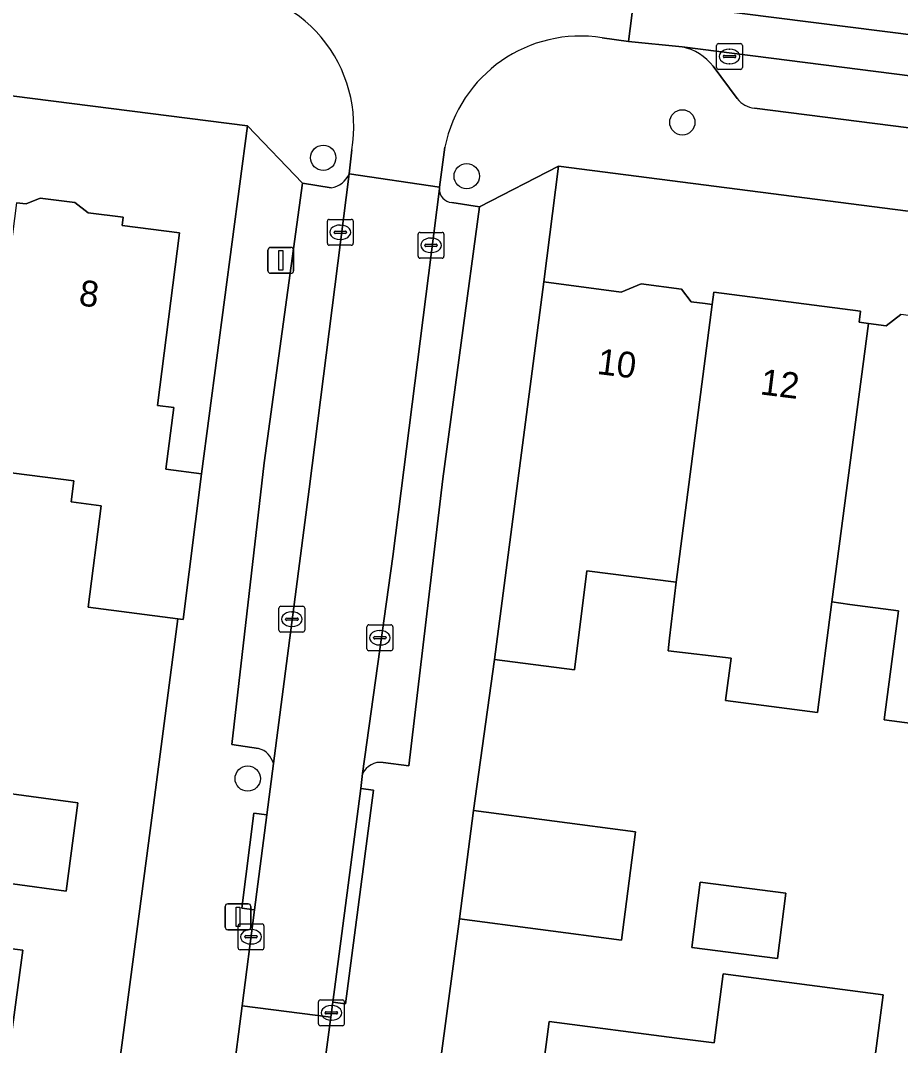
# Model space of a CAD drawing. Extents: x 161692 to 162379, y 380760 to 381678.
# Drawn here: x 161850.58 to 161884.64, y 381277.07 to 381316.74 of the extents above; entities that cross this region are included whole.
import ezdxf

# ---------------------------------------------------------------- set-up
doc = ezdxf.new("R2010")
doc.units = 0
for name, color, linetype in [('IMGEO_Boom', 7, 'Continuous'), ('IMGEO_Erf', 7, 'Continuous'), ('IMGEO_Kolk', 7, 'Continuous'), ('IMGEO_Lichtmast', 7, 'Continuous'), ('IMGEO_Muur', 7, 'Continuous'), ('IMGEO_Pand', 7, 'Continuous'), ('IMGEO_Pand_nummerreeks', 7, 'Continuous'), ('IMGEO_Parkeervlak_open', 7, 'Continuous'), ('IMGEO_Rijbaan_lokaal_gesloten', 7, 'Continuous'), ('IMGEO_Rijbaan_lokaal_open', 7, 'Continuous'), ('IMGEO_Voetpad_open', 7, 'Continuous')]:
    doc.layers.add(name, color=color, linetype=linetype)

msp = doc.modelspace()

# ---------------------------------------------------------------- linework, layer by layer
at = {"layer": 'IMGEO_Boom'}
for centre in [(161876.196, 381312.798), (161862.3, 381311.429), (161867.852, 381310.715), (161859.377, 381287.397)]:
    msp.add_circle(centre, 0.489, dxfattribs=at)
at = {"layer": 'IMGEO_Erf'}
for points in [[(161850.431, 381309.684), (161850.806, 381309.639), (161851.344, 381309.865), (161852.688, 381309.694), (161853.205, 381309.3), (161854.554, 381309.129), (161854.513, 381308.81), (161856.739, 381308.526), (161855.887, 381301.844), (161856.513, 381301.764), (161856.207, 381299.373), (161857.595, 381299.195), (161859.366, 381312.667), (161794.522, 381320.92)], [(161918.702, 381305.015), (161871.402, 381311.107), (161870.842, 381306.622), (161873.833, 381306.231), (161874.599, 381306.549), (161876.165, 381306.344), (161876.542, 381305.853), (161877.083, 381305.783), (161877.356, 381305.748), (161877.419, 381306.232), (161883.096, 381305.49), (161883.04, 381305.064), (161883.395, 381305.018), (161884.088, 381304.927), (161884.656, 381305.363)], [(161846.597, 381255.358), (161851.558, 381254.696), (161855.69, 381286.076), (161856.679, 381293.585), (161853.206, 381294.027), (161853.707, 381297.959), (161852.542, 381298.108), (161852.646, 381298.927), (161849.101, 381299.379)], [(161887.445, 381289.22), (161884.008, 381289.67), (161884.561, 381293.896), (161882.676, 381294.142), (161881.985, 381294.233), (161881.426, 381289.955), (161877.866, 381290.421), (161878.083, 381292.063), (161875.642, 381292.345), (161875.701, 381292.836), (161875.952, 381295.006), (161872.506, 381295.434), (161872.017, 381291.601), (161868.93, 381292.005), (161868.119, 381286.163), (161874.39, 381285.342), (161873.841, 381281.144), (161867.57, 381281.964), (161863.942, 381254.866), (161868.901, 381254.224), (161873.749, 381253.597), (161873.283, 381250)], [(161847.85, 381287.123), (161852.805, 381286.461), (161852.347, 381283.04), (161850.275, 381283.317)], [(161849.945, 381280.847), (161850.672, 381280.75), (161850.222, 381277.386)]]:
    msp.add_lwpolyline(points, dxfattribs=at)
for points in [[(161876.559, 381280.863), (161876.887, 381283.39), (161880.204, 381282.959), (161879.876, 381280.432)], [(161882.883, 381270.739), (161879.639, 381271.161), (161878.902, 381265.474), (161882.288, 381265.036), (161881.578, 381259.552), (161880.818, 381253.683), (161877.433, 381254.122), (161873.054, 381254.689), (161868.095, 381255.331), (161868.859, 381261.205), (161869.572, 381266.687), (161870.311, 381272.374), (161871.041, 381277.988), (161875.988, 381277.348), (161877.428, 381277.162), (161877.775, 381279.835), (161883.962, 381279.032)]]:
    msp.add_lwpolyline(points, close=True, dxfattribs=at)
at = {"layer": 'IMGEO_Kolk'}
for p, q in [((161877.522, 381314.922), (161877.522, 381315.774)), ((161877.597, 381315.848), (161878.449, 381315.848)), ((161878.01, 381315.628), (161878.035, 381315.628)), ((161878.523, 381315.774), (161878.523, 381314.922)), ((161877.781, 381315.342), (161877.781, 381315.354)), ((161878.219, 381315.305), (161877.821, 381315.305)), ((161877.824, 381315.391), (161878.222, 381315.391)), ((161878.265, 381315.354), (161878.265, 381315.342)), ((161878.449, 381314.848), (161877.597, 381314.848)), ((161878.033, 381315.068), (161878.008, 381315.068)), ((161862.46, 381308.117), (161862.46, 381308.969)), ((161862.535, 381309.043), (161863.387, 381309.043)), ((161862.948, 381308.823), (161862.973, 381308.823)), ((161863.461, 381308.969), (161863.461, 381308.117)), ((161862.719, 381308.537), (161862.719, 381308.549)), ((161863.157, 381308.5), (161862.759, 381308.5)), ((161862.762, 381308.586), (161863.16, 381308.586)), ((161863.203, 381308.549), (161863.203, 381308.537)), ((161865.971, 381307.614), (161865.971, 381308.466)), ((161866.046, 381308.54), (161866.898, 381308.54)), ((161866.972, 381308.466), (161866.972, 381307.614)), ((161863.387, 381308.043), (161862.535, 381308.043)), ((161862.971, 381308.263), (161862.946, 381308.263)), ((161866.23, 381308.034), (161866.23, 381308.046)), ((161866.273, 381308.083), (161866.671, 381308.083)), ((161866.459, 381308.32), (161866.484, 381308.32)), ((161866.714, 381308.046), (161866.714, 381308.034)), ((161866.668, 381307.997), (161866.27, 381307.997)), ((161866.482, 381307.76), (161866.457, 381307.76)), ((161866.898, 381307.54), (161866.046, 381307.54)), ((161860.586, 381293.14), (161860.586, 381293.992)), ((161860.661, 381294.066), (161861.513, 381294.066)), ((161861.074, 381293.846), (161861.099, 381293.846)), ((161861.587, 381293.992), (161861.587, 381293.14)), ((161860.845, 381293.56), (161860.845, 381293.572)), ((161861.283, 381293.523), (161860.885, 381293.523)), ((161860.888, 381293.609), (161861.286, 381293.609)), ((161861.329, 381293.572), (161861.329, 381293.56)), ((161864.067, 381293.348), (161864.919, 381293.348)), ((161861.513, 381293.066), (161860.661, 381293.066)), ((161861.097, 381293.286), (161861.072, 381293.286)), ((161863.992, 381292.422), (161863.992, 381293.274)), ((161864.48, 381293.128), (161864.505, 381293.128)), ((161864.993, 381293.274), (161864.993, 381292.422)), ((161864.251, 381292.842), (161864.251, 381292.854)), ((161864.689, 381292.805), (161864.291, 381292.805)), ((161864.294, 381292.891), (161864.692, 381292.891)), ((161864.503, 381292.568), (161864.478, 381292.568)), ((161864.735, 381292.854), (161864.735, 381292.842)), ((161864.919, 381292.348), (161864.067, 381292.348)), ((161859.004, 381280.848), (161859.004, 381281.7)), ((161859.079, 381281.774), (161859.931, 381281.774)), ((161859.492, 381281.554), (161859.517, 381281.554)), ((161860.005, 381281.7), (161860.005, 381280.848)), ((161859.263, 381281.268), (161859.263, 381281.28)), ((161859.701, 381281.231), (161859.303, 381281.231)), ((161859.306, 381281.317), (161859.704, 381281.317)), ((161859.747, 381281.28), (161859.747, 381281.268)), ((161859.931, 381280.774), (161859.079, 381280.774)), ((161859.515, 381280.994), (161859.49, 381280.994)), ((161862.115, 381277.903), (161862.115, 381278.755)), ((161862.19, 381278.829), (161863.042, 381278.829)), ((161863.116, 381278.755), (161863.116, 381277.903)), ((161862.374, 381278.323), (161862.374, 381278.335)), ((161862.812, 381278.286), (161862.414, 381278.286)), ((161862.417, 381278.372), (161862.815, 381278.372)), ((161862.603, 381278.609), (161862.628, 381278.609)), ((161862.858, 381278.335), (161862.858, 381278.323)), ((161862.626, 381278.049), (161862.601, 381278.049)), ((161863.042, 381277.829), (161862.19, 381277.829))]:
    msp.add_line(p, q, dxfattribs=at)
for points in [[(161877.522, 381314.922), (161877.522, 381315.774)], [(161877.597, 381315.848), (161878.449, 381315.848)], [(161878.523, 381315.774), (161878.523, 381314.922)], [(161878.449, 381314.848), (161877.597, 381314.848)], [(161862.46, 381308.117), (161862.46, 381308.969)], [(161862.535, 381309.043), (161863.387, 381309.043)], [(161863.461, 381308.969), (161863.461, 381308.117)], [(161865.971, 381307.614), (161865.971, 381308.466)], [(161866.046, 381308.54), (161866.898, 381308.54)], [(161866.972, 381308.466), (161866.972, 381307.614)], [(161863.387, 381308.043), (161862.535, 381308.043)], [(161866.898, 381307.54), (161866.046, 381307.54)], [(161860.586, 381293.14), (161860.586, 381293.992)], [(161860.661, 381294.066), (161861.513, 381294.066)], [(161861.587, 381293.992), (161861.587, 381293.14)], [(161864.067, 381293.348), (161864.919, 381293.348)], [(161861.513, 381293.066), (161860.661, 381293.066)], [(161863.992, 381292.422), (161863.992, 381293.274)], [(161864.993, 381293.274), (161864.993, 381292.422)], [(161864.919, 381292.348), (161864.067, 381292.348)], [(161859.004, 381280.848), (161859.004, 381281.7)], [(161859.079, 381281.774), (161859.931, 381281.774)], [(161860.005, 381281.7), (161860.005, 381280.848)], [(161859.931, 381280.774), (161859.079, 381280.774)], [(161862.115, 381277.903), (161862.115, 381278.755)], [(161862.19, 381278.829), (161863.042, 381278.829)], [(161863.116, 381278.755), (161863.116, 381277.903)], [(161863.042, 381277.829), (161862.19, 381277.829)]]:
    msp.add_lwpolyline(points, dxfattribs=at)
for centre, radius, start, end in [((161877.599, 381315.772), 0.0765, 91.552, 178.448), ((161877.599, 381315.772), 0.0765, 91.552, 178.448), ((161878.447, 381315.772), 0.0765, 1.552, 88.448), ((161878.447, 381315.772), 0.0765, 1.552, 88.448), ((161877.821, 381315.351), 0.0403, 85.8775, 175.7526), ((161877.818, 381315.341), 0.0366, 178.938, 274.7102), ((161878.222, 381315.348), 0.043, 264.8664, 352.4533), ((161878.226, 381315.353), 0.0386, 1.7309, 96.639), ((161877.599, 381314.924), 0.0765, 181.552, 268.448), ((161877.599, 381314.924), 0.0765, 181.552, 268.448), ((161878.447, 381314.924), 0.0765, 271.552, 358.448), ((161878.447, 381314.924), 0.0765, 271.552, 358.448), ((161862.537, 381308.967), 0.0765, 91.552, 178.448), ((161862.537, 381308.967), 0.0765, 91.552, 178.448), ((161863.385, 381308.967), 0.0765, 1.552, 88.448), ((161863.385, 381308.967), 0.0765, 1.552, 88.448), ((161862.759, 381308.546), 0.0403, 85.8775, 175.7526), ((161862.756, 381308.536), 0.0366, 178.938, 274.7102), ((161863.16, 381308.543), 0.043, 264.8664, 352.4533), ((161863.164, 381308.548), 0.0386, 1.7309, 96.639), ((161866.048, 381308.464), 0.0765, 91.552, 178.448), ((161866.048, 381308.464), 0.0765, 91.552, 178.448), ((161866.896, 381308.464), 0.0765, 1.552, 88.448), ((161866.896, 381308.464), 0.0765, 1.552, 88.448), ((161862.537, 381308.119), 0.0765, 181.552, 268.448), ((161862.537, 381308.119), 0.0765, 181.552, 268.448), ((161863.385, 381308.119), 0.0765, 271.552, 358.448), ((161863.385, 381308.119), 0.0765, 271.552, 358.448), ((161866.27, 381308.043), 0.0403, 85.8775, 175.7526), ((161866.267, 381308.033), 0.0366, 178.938, 274.7102), ((161866.671, 381308.04), 0.043, 264.8664, 352.4533), ((161866.675, 381308.045), 0.0386, 1.7309, 96.639), ((161866.048, 381307.616), 0.0765, 181.552, 268.448), ((161866.048, 381307.616), 0.0765, 181.552, 268.448), ((161866.896, 381307.616), 0.0765, 271.552, 358.448), ((161866.896, 381307.616), 0.0765, 271.552, 358.448), ((161860.663, 381293.99), 0.0765, 91.552, 178.448), ((161860.663, 381293.99), 0.0765, 91.552, 178.448), ((161861.511, 381293.99), 0.0765, 1.552, 88.448), ((161861.511, 381293.99), 0.0765, 1.552, 88.448), ((161860.885, 381293.569), 0.0403, 85.8775, 175.7526), ((161860.882, 381293.559), 0.0366, 178.938, 274.7102), ((161861.286, 381293.566), 0.043, 264.8664, 352.4533), ((161861.29, 381293.571), 0.0386, 1.7309, 96.639), ((161864.069, 381293.272), 0.0765, 91.552, 178.448), ((161864.069, 381293.272), 0.0765, 91.552, 178.448), ((161864.917, 381293.272), 0.0765, 1.552, 88.448), ((161864.917, 381293.272), 0.0765, 1.552, 88.448), ((161860.663, 381293.142), 0.0765, 181.552, 268.448), ((161860.663, 381293.142), 0.0765, 181.552, 268.448), ((161861.511, 381293.142), 0.0765, 271.552, 358.448), ((161861.511, 381293.142), 0.0765, 271.552, 358.448), ((161864.291, 381292.851), 0.0403, 85.8775, 175.7526), ((161864.288, 381292.841), 0.0366, 178.938, 274.7102), ((161864.692, 381292.848), 0.043, 264.8664, 352.4533), ((161864.696, 381292.853), 0.0386, 1.7309, 96.639), ((161864.069, 381292.424), 0.0765, 181.552, 268.448), ((161864.069, 381292.424), 0.0765, 181.552, 268.448), ((161864.917, 381292.424), 0.0765, 271.552, 358.448), ((161864.917, 381292.424), 0.0765, 271.552, 358.448), ((161859.081, 381281.698), 0.0765, 91.552, 178.448), ((161859.081, 381281.698), 0.0765, 91.552, 178.448), ((161859.929, 381281.698), 0.0765, 1.552, 88.448), ((161859.929, 381281.698), 0.0765, 1.552, 88.448), ((161859.303, 381281.277), 0.0403, 85.8775, 175.7526), ((161859.3, 381281.267), 0.0366, 178.938, 274.7102), ((161859.704, 381281.274), 0.043, 264.8664, 352.4533), ((161859.708, 381281.279), 0.0386, 1.7309, 96.639), ((161859.081, 381280.85), 0.0765, 181.552, 268.448), ((161859.081, 381280.85), 0.0765, 181.552, 268.448), ((161859.929, 381280.85), 0.0765, 271.552, 358.448), ((161859.929, 381280.85), 0.0765, 271.552, 358.448), ((161862.192, 381278.753), 0.0765, 91.552, 178.448), ((161862.192, 381278.753), 0.0765, 91.552, 178.448), ((161863.04, 381278.753), 0.0765, 1.552, 88.448), ((161863.04, 381278.753), 0.0765, 1.552, 88.448), ((161862.414, 381278.332), 0.0403, 85.8775, 175.7526), ((161862.411, 381278.322), 0.0366, 178.938, 274.7102), ((161862.815, 381278.329), 0.043, 264.8664, 352.4533), ((161862.819, 381278.334), 0.0386, 1.7309, 96.639), ((161862.192, 381277.905), 0.0765, 181.552, 268.448), ((161862.192, 381277.905), 0.0765, 181.552, 268.448), ((161863.04, 381277.905), 0.0765, 271.552, 358.448), ((161863.04, 381277.905), 0.0765, 271.552, 358.448)]:
    msp.add_arc(centre, radius, start, end, dxfattribs=at)
for centre, major_axis, ratio, start_param, end_param in [((161878.009, 381315.348), (-0.387, 0.002), 0.722429, 4.712389, 7.853982), ((161878.034, 381315.348), (-0.39, 0.002), 0.717154, 1.570796, 4.712389), ((161862.947, 381308.543), (-0.387, 0.002), 0.722429, 4.712389, 7.853982), ((161862.972, 381308.543), (-0.39, 0.002), 0.717154, 1.570796, 4.712389), ((161866.458, 381308.04), (-0.387, 0.002), 0.722429, 4.712389, 7.853982), ((161866.483, 381308.04), (-0.39, 0.002), 0.717154, 1.570796, 4.712389), ((161861.073, 381293.566), (-0.387, 0.002), 0.722429, 4.712389, 7.853982), ((161861.098, 381293.566), (-0.39, 0.002), 0.717154, 1.570796, 4.712389), ((161864.479, 381292.848), (-0.387, 0.002), 0.722429, 4.712389, 7.853982), ((161864.504, 381292.848), (-0.39, 0.002), 0.717154, 1.570796, 4.712389), ((161859.491, 381281.274), (-0.387, 0.002), 0.722429, 4.712389, 7.853982), ((161859.516, 381281.274), (-0.39, 0.002), 0.717154, 1.570796, 4.712389), ((161862.602, 381278.329), (-0.387, 0.002), 0.722429, 4.712389, 7.853982), ((161862.627, 381278.329), (-0.39, 0.002), 0.717154, 1.570796, 4.712389)]:
    msp.add_ellipse(centre, major_axis=major_axis, ratio=ratio, start_param=start_param, end_param=end_param, dxfattribs=at)
at = {"layer": 'IMGEO_Lichtmast'}
for p, q in [((161860.162, 381307.057), (161860.162, 381307.857)), ((161860.162, 381307.857), (161860.162, 381307.057)), ((161860.262, 381307.957), (161861.052, 381307.957)), ((161861.052, 381307.957), (161860.262, 381307.957)), ((161861.152, 381307.857), (161861.152, 381307.057)), ((161861.152, 381307.057), (161861.152, 381307.857)), ((161861.052, 381306.957), (161860.262, 381306.957)), ((161860.262, 381306.957), (161861.052, 381306.957)), ((161858.506, 381281.646), (161858.506, 381282.446)), ((161858.506, 381282.446), (161858.506, 381281.646)), ((161858.606, 381282.546), (161859.396, 381282.546)), ((161859.396, 381282.546), (161858.606, 381282.546)), ((161859.496, 381282.446), (161859.496, 381281.646)), ((161859.496, 381281.646), (161859.496, 381282.446)), ((161859.396, 381281.546), (161858.606, 381281.546)), ((161858.606, 381281.546), (161859.396, 381281.546))]:
    msp.add_line(p, q, dxfattribs=at)
for points in [[(161860.582, 381307.832), (161860.732, 381307.832), (161860.732, 381307.082), (161860.582, 381307.082), (161860.582, 381307.832)], [(161858.926, 381282.421), (161859.076, 381282.421), (161859.076, 381281.671), (161858.926, 381281.671), (161858.926, 381282.421)]]:
    msp.add_lwpolyline(points, dxfattribs=at)
for centre, start, end in [((161860.262, 381307.857), 90, 180), ((161860.262, 381307.857), 90, 180), ((161861.052, 381307.857), 0, 90), ((161861.052, 381307.857), 360, 90), ((161860.262, 381307.057), 180, 270), ((161860.262, 381307.057), 180, 270), ((161861.052, 381307.057), 270, 0), ((161861.052, 381307.057), 270, 0), ((161858.606, 381282.446), 90, 180), ((161858.606, 381282.446), 90, 180), ((161859.396, 381282.446), 0, 90), ((161859.396, 381282.446), 360, 90), ((161858.606, 381281.646), 180, 270), ((161858.606, 381281.646), 180, 270), ((161859.396, 381281.646), 270, 0), ((161859.396, 381281.646), 270, 0)]:
    msp.add_arc(centre, 0.1, start, end, dxfattribs=at)
at = {"layer": 'IMGEO_Muur'}
for points in [[(161856.679, 381293.585), (161855.69, 381286.076)], [(161868.93, 381292.005), (161868.119, 381286.163)]]:
    msp.add_lwpolyline(points, dxfattribs=at)
at = {"layer": 'IMGEO_Pand'}
for points in [[(161849.101, 381299.379), (161852.646, 381298.927), (161852.542, 381298.108), (161853.707, 381297.959), (161853.206, 381294.027), (161856.679, 381293.585), (161856.876, 381293.56), (161857.595, 381299.195), (161856.207, 381299.373), (161856.513, 381301.764), (161855.887, 381301.844), (161856.739, 381308.526), (161854.513, 381308.81), (161854.554, 381309.129), (161853.205, 381309.3), (161852.688, 381309.694), (161851.344, 381309.865), (161850.806, 381309.639), (161850.431, 381309.684)], [(161877.356, 381305.748), (161877.083, 381305.783), (161876.542, 381305.853), (161876.165, 381306.344), (161874.599, 381306.549), (161873.833, 381306.231), (161870.842, 381306.622), (161868.93, 381292.005), (161872.017, 381291.601), (161872.506, 381295.434), (161875.952, 381295.006)], [(161883.395, 381305.018), (161883.04, 381305.064), (161883.096, 381305.49), (161877.419, 381306.232), (161877.356, 381305.748), (161875.952, 381295.006), (161875.701, 381292.836), (161875.642, 381292.345), (161878.083, 381292.063), (161877.866, 381290.421), (161881.426, 381289.955), (161881.985, 381294.233)], [(161889.792, 381304.253), (161886.702, 381304.657), (161886.327, 381305.144), (161884.656, 381305.363), (161884.088, 381304.927), (161883.395, 381305.018), (161881.985, 381294.233), (161882.676, 381294.142), (161884.561, 381293.896), (161884.008, 381289.67), (161887.445, 381289.22), (161887.821, 381289.171)], [(161838.404, 381284.864), (161836.685, 381285.121), (161836.322, 381282.331), (161835.92, 381279.248), (161839.658, 381278.761), (161850.222, 381277.386), (161850.672, 381280.75), (161849.945, 381280.847), (161850.275, 381283.317), (161852.347, 381283.04), (161852.805, 381286.461), (161847.85, 381287.123), (161847.313, 381287.195), (161846.846, 381283.703), (161842.013, 381284.349), (161840.434, 381284.56)], [(161868.119, 381286.163), (161867.57, 381281.964), (161873.841, 381281.144), (161874.39, 381285.342)], [(161876.559, 381280.863), (161879.876, 381280.432), (161880.204, 381282.959), (161876.887, 381283.39)], [(161870.311, 381272.374), (161879.639, 381271.161), (161882.883, 381270.739), (161883.962, 381279.032), (161877.775, 381279.835), (161877.428, 381277.162), (161875.988, 381277.348), (161871.041, 381277.988)]]:
    msp.add_lwpolyline(points, close=True, dxfattribs=at)
at = {"layer": 'IMGEO_Parkeervlak_open'}
for points in [[(161917.21, 381310.5), (161876.187, 381315.72)], [(161877.391, 381314.969), (161878.321, 381313.716)], [(161878.988, 381313.353), (161913.61, 381308.931)], [(161860.369, 381287.975), (161861.761, 381298.603), (161863.306, 381310.81)], [(161862.608, 381310.266), (161861.491, 381310.444), (161860.014, 381299.613), (161858.769, 381288.718), (161859.797, 381288.563)], [(161866.793, 381310.228), (161864.987, 381295.988), (161863.824, 381287.593)], [(161866.932, 381299.002), (161868.344, 381309.528), (161867.278, 381309.693)], [(161864.621, 381288.019), (161865.611, 381287.89), (161866.932, 381299.002)]]:
    msp.add_lwpolyline(points, dxfattribs=at)
for centre, radius, start, end in [((161875.79, 381313.743), 2.016, 37.442, 78.6499), ((161879.062, 381314.284), 0.934, 217.4585, 265.4289), ((161862.472, 381311.16), 0.904, 278.6254, 337.2381), ((161867.315, 381310.214), 0.523, 178.4991, 265.8882), ((161859.591, 381287.79), 0.8, 13.366, 75.0536), ((161864.518, 381287.254), 0.772, 82.2985, 153.9509)]:
    msp.add_arc(centre, radius, start, end, dxfattribs=at)
at = {"layer": 'IMGEO_Rijbaan_lokaal_gesloten'}
msp.add_lwpolyline([(161924.113, 381311.254), (161874.322, 381317.556), (161874.117, 381315.93), (161876.187, 381315.72), (161917.21, 381310.5), (161917.275, 381310.497), (161923.115, 381309.763), (161949.317, 381306.399), (161975.89, 381302.987), (162013.612, 381298.115), (162013.834, 381299.74), (161976.139, 381304.58)], close=True, dxfattribs=at)
at = {"layer": 'IMGEO_Rijbaan_lokaal_open'}
for points in [[(161873.096, 381316.072), (161874.117, 381315.93), (161874.322, 381317.556), (161874.551, 381319.364), (161874.726, 381320.753), (161875.004, 381322.955)], [(161863.408, 381311.731), (161863.306, 381310.81), (161866.801, 381310.288), (161867.011, 381311.834)]]:
    msp.add_lwpolyline(points, dxfattribs=at)
for points in [[(161874.551, 381319.364), (161874.322, 381317.556), (161924.113, 381311.254), (161976.139, 381304.58), (162013.834, 381299.74), (162014.081, 381301.54), (161976.129, 381306.423), (161924.33, 381313.049)], [(161864.987, 381295.988), (161866.793, 381310.228), (161866.801, 381310.288), (161863.306, 381310.81), (161861.761, 381298.603), (161860.369, 381287.975), (161860.114, 381285.992), (161859.641, 381282.316), (161859.161, 381278.6), (161862.595, 381278.164), (161862.671, 381278.748), (161863.751, 381287.017), (161863.824, 381287.593)], [(161859.161, 381278.6), (161858.787, 381275.704), (161858.749, 381275.573), (161862.265, 381275.153), (161862.226, 381275.343), (161862.595, 381278.164)]]:
    msp.add_lwpolyline(points, close=True, dxfattribs=at)
for centre, radius, start, end in [((161858.11, 381312.632), 5.374, 350.3458, 89.7789), ((161872.253, 381310.795), 5.344, 80.9255, 168.7863)]:
    msp.add_arc(centre, radius, start, end, dxfattribs=at)
at = {"layer": 'IMGEO_Voetpad_open'}
for points in [[(161793.919, 381324.068), (161793.381, 381321.065), (161794.522, 381320.92), (161859.366, 381312.667), (161861.491, 381310.444), (161862.608, 381310.266)], [(161876.187, 381315.72), (161874.117, 381315.93), (161873.096, 381316.072)], [(161878.321, 381313.716), (161877.391, 381314.969)], [(161913.61, 381308.931), (161878.988, 381313.353)], [(161859.797, 381288.563), (161858.769, 381288.718), (161860.014, 381299.613), (161861.491, 381310.444), (161859.366, 381312.667), (161857.595, 381299.195), (161856.876, 381293.56), (161856.679, 381293.585), (161855.69, 381286.076), (161851.558, 381254.696), (161851.417, 381253.627), (161847.794, 381226.116), (161849.227, 381222.46), (161851.563, 381216.501), (161855.472, 381206.468), (161856.733, 381203.329), (161860.289, 381205.724), (161859.567, 381207.59)], [(161863.306, 381310.81), (161863.408, 381311.731)], [(161867.011, 381311.834), (161866.801, 381310.288), (161866.793, 381310.228)], [(161870.842, 381306.622), (161871.402, 381311.107), (161868.344, 381309.528), (161866.932, 381299.002), (161865.611, 381287.89), (161864.621, 381288.019)], [(161867.278, 381309.693), (161868.344, 381309.528), (161871.402, 381311.107), (161918.702, 381305.015), (161921.176, 381304.696), (162000, 381294.145), (162015.076, 381292.22), (162011.546, 381263.36), (162011.205, 381260.006), (162013.191, 381260.844), (162013.658, 381259.636)], [(161858.57, 381247.065), (161858.195, 381244.036), (161857.888, 381241.555), (161862.21, 381241.483), (161863.08, 381248.208), (161863.312, 381250), (161863.942, 381254.866), (161867.57, 381281.964), (161868.119, 381286.163), (161868.93, 381292.005), (161870.842, 381306.622)], [(161858.749, 381275.573), (161858.787, 381275.704), (161859.161, 381278.6), (161859.641, 381282.316), (161859.145, 381282.378), (161859.618, 381286.054), (161860.114, 381285.992), (161860.369, 381287.975)], [(161863.824, 381287.593), (161863.751, 381287.017), (161864.246, 381286.953), (161863.166, 381278.684), (161862.671, 381278.748), (161862.595, 381278.164), (161862.226, 381275.343), (161862.265, 381275.153)]]:
    msp.add_lwpolyline(points, dxfattribs=at)
for points in [[(161862.671, 381278.748), (161863.166, 381278.684), (161864.246, 381286.953), (161863.751, 381287.017)], [(161860.114, 381285.992), (161859.618, 381286.054), (161859.145, 381282.378), (161859.641, 381282.316)]]:
    msp.add_lwpolyline(points, close=True, dxfattribs=at)
for centre, radius, start, end in [((161858.11, 381312.632), 5.374, 350.3458, 89.7789), ((161872.253, 381310.795), 5.344, 80.9255, 168.7863), ((161875.79, 381313.743), 2.016, 37.442, 78.6499), ((161879.062, 381314.284), 0.934, 217.4585, 265.4289), ((161862.472, 381311.16), 0.904, 278.6254, 337.2381), ((161867.315, 381310.214), 0.523, 178.4991, 265.8882), ((161859.591, 381287.79), 0.8, 13.366, 75.0536), ((161864.518, 381287.254), 0.772, 82.2985, 153.9509)]:
    msp.add_arc(centre, radius, start, end, dxfattribs=at)

# ---------------------------------------------------------------- texts
at = {"layer": 'IMGEO_Pand_nummerreeks'}
for s, rotation, p in [('8', 352.7293, (161852.812, 381305.72)), ('10', 352.8724, (161872.867, 381303.063)), ('12', 352.8724, (161879.177, 381302.274))]:
    msp.add_text(s, height=1, rotation=rotation, dxfattribs=at).set_placement(p)

doc.saveas('drawing.dxf')
